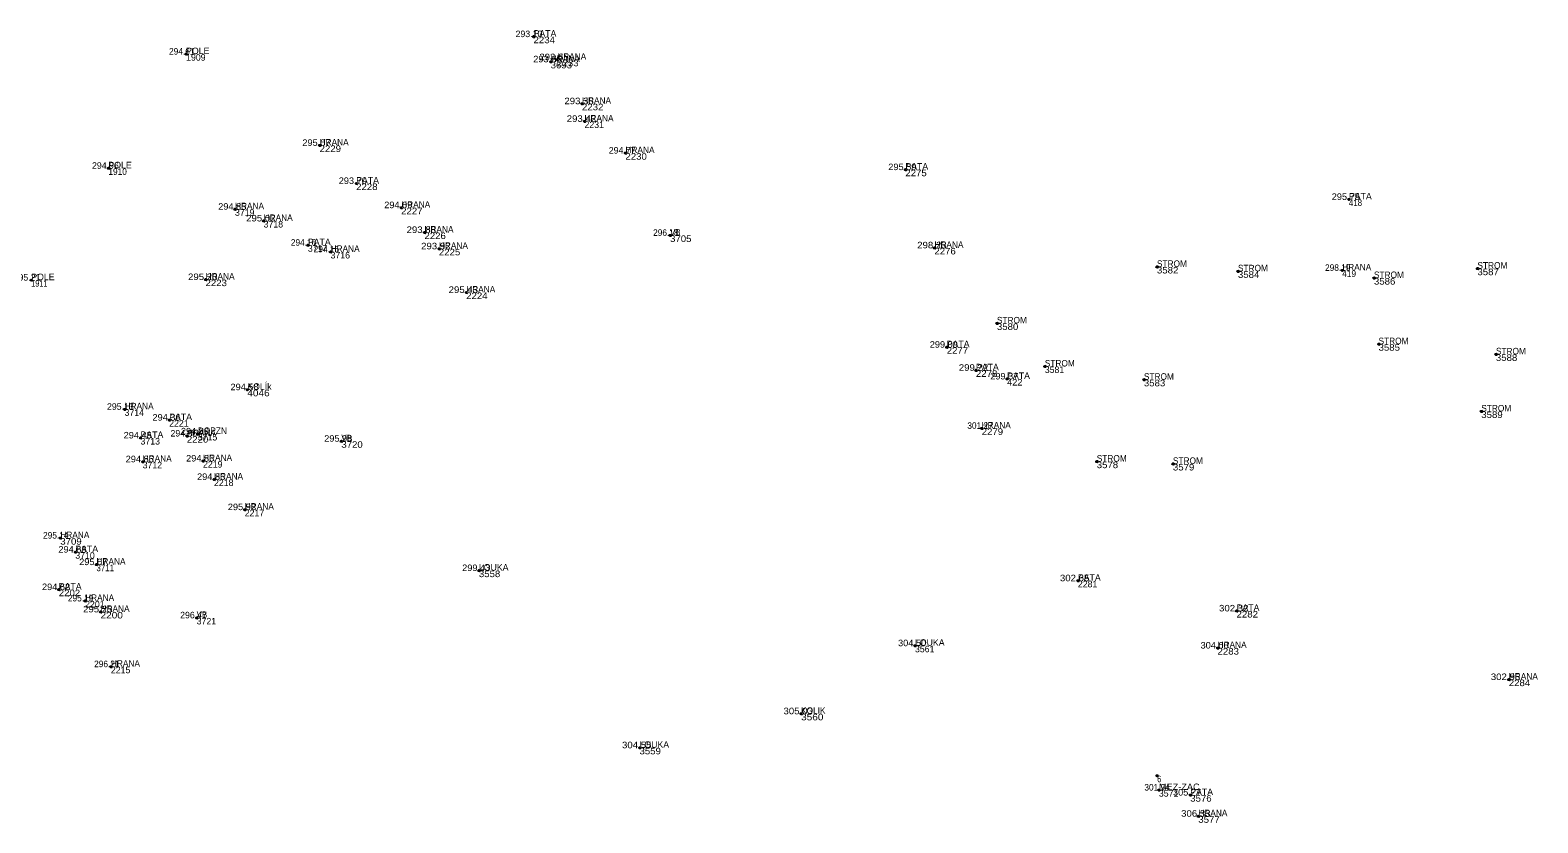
# Model space of a CAD drawing. Extents: x -565336 to -561834, y -1146819 to -1145270.
# Drawn here: x -563916.6 to -563838.2, y -1145848.1 to -1145806.8 of the extents above; entities that cross this region are included whole.
import ezdxf
from ezdxf.enums import TextEntityAlignment as Align

# ---------------------------------------------------------------- set-up
doc = ezdxf.new("R2010")
doc.units = 0
doc.header["$LTSCALE"] = 0.14
doc.header["$PDMODE"] = 32
doc.header["$PDSIZE"] = 0.07
for name, color, linetype in [('40', 7, 'Continuous'), ('43', 7, 'Continuous'), ('44', 7, 'Continuous'), ('45', 7, 'Continuous')]:
    doc.layers.add(name, color=color, linetype=linetype)

msp = doc.modelspace()

# ---------------------------------------------------------------- linework, layer by layer
at = {"layer": '40'}
for p in [(-563890.44, -1145807.15), (-563908.5, -1145808.06), (-563889.55, -1145808.46), (-563889.21, -1145808.35), (-563887.92, -1145810.64), (-563887.79, -1145811.56), (-563901.56, -1145812.81), (-563885.66, -1145813.21), (-563912.54, -1145814), (-563871.11, -1145814.07), (-563899.66, -1145814.79), (-563848.05, -1145815.62), (-563905.96, -1145816.13), (-563897.32, -1145816.05), (-563904.47, -1145816.74), (-563896.11, -1145817.34), (-563902.17, -1145818), (-563895.36, -1145818.19), (-563883.34, -1145817.49), (-563869.6, -1145818.14), (-563900.99, -1145818.35), (-563858.03, -1145819.13), (-563853.82, -1145819.36), (-563848.4, -1145819.31), (-563846.75, -1145819.71), (-563841.37, -1145819.22), (-563916.55, -1145819.82), (-563907.49, -1145819.79), (-563893.94, -1145820.46), (-563866.35, -1145822.07), (-563868.96, -1145823.31), (-563846.51, -1145823.15), (-563840.41, -1145823.68), (-563863.86, -1145824.31), (-563867.44, -1145824.51), (-563865.82, -1145824.96), (-563858.71, -1145825), (-563905.32, -1145825.52), (-563911.7, -1145826.54), (-563841.17, -1145826.65), (-563909.38, -1145827.1), (-563867.14, -1145827.53), (-563910.87, -1145828.03), (-563908.46, -1145827.93), (-563907.89, -1145827.82), (-563900.43, -1145828.2), (-563910.76, -1145829.27), (-563907.62, -1145829.23), (-563861.16, -1145829.26), (-563857.2, -1145829.38), (-563907.05, -1145830.19), (-563905.45, -1145831.76), (-563915.04, -1145833.24), (-563914.26, -1145833.97), (-563913.16, -1145834.62), (-563893.28, -1145834.93), (-563915.12, -1145835.92), (-563862.14, -1145835.46), (-563913.75, -1145836.51), (-563912.95, -1145837.08), (-563907.95, -1145837.39), (-563853.89, -1145837.03), (-563870.61, -1145838.84), (-563854.88, -1145838.96), (-563912.41, -1145839.93), (-563839.74, -1145840.6), (-563876.53, -1145842.38), (-563884.93, -1145844.15), (-563858.02, -1145845.6), (-563857.93, -1145846.35), (-563856.3, -1145846.61), (-563855.88, -1145847.71)]:
    msp.add_point(p, dxfattribs=at)

# ---------------------------------------------------------------- texts
at = {"layer": '43'}
for s, width, p in [('2234', 1.1, (-563890.44, -1145807.49)), ('3693', 1.1, (-563889.55, -1145808.8)), ('2233', 1.1, (-563889.21, -1145808.69)), ('2232', 1.1, (-563887.92, -1145810.98)), ('2229', 1.1, (-563901.56, -1145813.15)), ('2230', 1.1, (-563885.66, -1145813.55)), ('1910', 0.95, (-563912.54, -1145814.34)), ('2275', 1.1, (-563871.11, -1145814.41)), ('2228', 1.1, (-563899.66, -1145815.13)), ('418', 0.9, (-563848.05, -1145815.96)), ('2227', 1.1, (-563897.32, -1145816.39)), ('2226', 1.1, (-563896.11, -1145817.68)), ('3705', 1.1, (-563883.34, -1145817.83)), ('2276', 1.1, (-563869.6, -1145818.48)), ('2225', 1.1, (-563895.36, -1145818.53)), ('3582', 1.1, (-563858.03, -1145819.47)), ('3584', 1.1, (-563853.82, -1145819.7)), ('419', 0.95, (-563848.4, -1145819.65)), ('3586', 1.1, (-563846.75, -1145820.05)), ('3587', 1.1, (-563841.37, -1145819.56)), ('1911', 0.8, (-563916.55, -1145820.16)), ('2223', 1.1, (-563907.49, -1145820.13)), ('2224', 1.1, (-563893.94, -1145820.8)), ('3580', 1.1, (-563866.35, -1145822.41)), ('2277', 1.1, (-563868.96, -1145823.65)), ('3585', 1.1, (-563846.51, -1145823.49)), ('3588', 1.1, (-563840.41, -1145824.02)), ('2278', 1.1, (-563867.44, -1145824.85)), ('422', 1.05, (-563865.82, -1145825.3)), ('3583', 1.1, (-563858.71, -1145825.34)), ('4046', 1.15, (-563905.32, -1145825.86)), ('3589', 1.1, (-563841.17, -1145826.99)), ('2279', 1.1, (-563867.14, -1145827.87)), ('2220', 1.1, (-563908.46, -1145828.27)), ('3720', 1.1, (-563900.43, -1145828.54)), ('3578', 1.1, (-563861.16, -1145829.6)), ('3579', 1.1, (-563857.2, -1145829.72)), ('3709', 1.1, (-563915.04, -1145833.58)), ('3711', 0.9, (-563913.16, -1145834.96)), ('3558', 1.1, (-563893.28, -1145835.27)), ('2202', 1.1, (-563915.12, -1145836.26)), ('2200', 1.15, (-563912.95, -1145837.42)), ('2282', 1.1, (-563853.89, -1145837.37)), ('2283', 1.1, (-563854.88, -1145839.3)), ('2284', 1.1, (-563839.74, -1145840.94)), ('3560', 1.15, (-563876.53, -1145842.72)), ('3559', 1.1, (-563884.93, -1145844.49)), ('6', 0.85, (-563858.02, -1145845.94)), ('3576', 1.1, (-563856.3, -1145846.95)), ('3577', 1.1, (-563855.88, -1145848.05))]:
    msp.add_text(s, height=0.34, dxfattribs=dict(at, width=width)).set_placement(p)
for s, p in [('1909', (-563908.5, -1145808.4)), ('2231', (-563887.79, -1145811.9)), ('3719', (-563905.96, -1145816.47)), ('3718', (-563904.47, -1145817.08)), ('3717', (-563902.17, -1145818.34)), ('3716', (-563900.99, -1145818.69)), ('3581', (-563863.86, -1145824.65)), ('3714', (-563911.7, -1145826.88)), ('2221', (-563909.38, -1145827.44)), ('3713', (-563910.87, -1145828.37)), ('3715', (-563907.89, -1145828.16)), ('3712', (-563910.76, -1145829.61)), ('2219', (-563907.62, -1145829.57)), ('2218', (-563907.05, -1145830.53)), ('2217', (-563905.45, -1145832.1)), ('3710', (-563914.26, -1145834.31)), ('2281', (-563862.14, -1145835.8)), ('2201', (-563913.75, -1145836.85)), ('3721', (-563907.95, -1145837.73)), ('3561', (-563870.61, -1145839.18)), ('2215', (-563912.41, -1145840.27)), ('3571', (-563857.93, -1145846.69))]:
    msp.add_text(s, height=0.34, dxfattribs=at).set_placement(p)
at = {"layer": '44'}
for s, p in [('293.10', (-563890.677, -1145807.174)), ('294.77', (-563885.8315, -1145813.234)), ('294.96', (-563912.695, -1145814.024)), ('295.21', (-563916.7695, -1145819.844)), ('295.13', (-563911.917, -1145826.564)), ('294.96', (-563908.615, -1145827.954)), ('296.47', (-563908.1135, -1145837.414))]:
    msp.add_text(s, height=0.34, dxfattribs=at).set_placement(p, align=Align.CENTER)
for s, width, p in [('294.61', 0.95, (-563908.725, -1145808.084)), ('293.66', 1.05, (-563889.7225, -1145808.484)), ('293.65', 1.1, (-563889.3735, -1145808.374)), ('293.38', 1.1, (-563888.0715, -1145810.664)), ('293.42', 1.1, (-563887.948, -1145811.584)), ('295.07', 1.05, (-563901.7275, -1145812.834)), ('295.59', 1.05, (-563871.2655, -1145814.094)), ('293.70', 1.05, (-563899.8355, -1145814.814)), ('294.85', 1.05, (-563906.1005, -1145816.154)), ('294.09', 1.05, (-563897.47, -1145816.074)), ('295.75', 1.05, (-563848.2135, -1145815.644)), ('295.02', 1.1, (-563904.6145, -1145816.764)), ('293.88', 1.1, (-563896.2735, -1145817.364)), ('296.18', 0.95, (-563883.561, -1145817.514)), ('294.16', 0.95, (-563902.395, -1145818.024)), ('294.15', 0.95, (-563901.2055, -1145818.374)), ('293.92', 1.1, (-563895.518, -1145818.214)), ('298.23', 1.1, (-563869.7285, -1145818.164)), ('295.20', 1.1, (-563907.6345, -1145819.814)), ('298.19', 0.95, (-563848.6305, -1145819.334)), ('295.43', 1.1, (-563894.0875, -1145820.484)), ('299.09', 1.05, (-563869.11, -1145823.334)), ('299.22', 1.1, (-563867.566, -1145824.534)), ('294.58', 1.05, (-563905.462, -1145825.544)), ('299.37', 1.05, (-563865.966, -1145824.984)), ('294.36', 1.05, (-563909.518, -1145827.124)), ('294.89', 1.05, (-563908.04, -1145827.844)), ('301.27', 0.95, (-563867.227, -1145827.554)), ('294.45', 1.05, (-563911.016, -1145828.054)), ('295.98', 1.05, (-563900.5905, -1145828.224)), ('294.86', 1.05, (-563910.91, -1145829.294)), ('294.86', 1.05, (-563907.77, -1145829.254)), ('294.86', 1.05, (-563907.2, -1145830.214)), ('295.92', 1.05, (-563905.6, -1145831.784)), ('295.14', 0.95, (-563915.2745, -1145833.264)), ('294.68', 1.05, (-563914.411, -1145833.994)), ('295.07', 1.05, (-563913.3275, -1145834.644)), ('299.43', 1.05, (-563893.418, -1145834.954)), ('302.65', 1.1, (-563862.309, -1145835.484)), ('294.62', 1.05, (-563915.2605, -1145835.944)), ('295.19', 0.95, (-563913.9845, -1145836.534)), ('295.25', 1.1, (-563913.0905, -1145837.104)), ('302.32', 1.1, (-563854.036, -1145837.054)), ('304.50', 1.05, (-563870.7585, -1145838.864)), ('304.00', 1.05, (-563855.0325, -1145838.984)), ('296.21', 0.95, (-563912.62, -1145839.954)), ('302.95', 1.1, (-563839.909, -1145840.624)), ('305.03', 1.1, (-563876.68, -1145842.404)), ('304.55', 1.1, (-563885.0745, -1145844.174)), ('301.94', 0.95, (-563858.0235, -1145846.374)), ('305.27', 1.05, (-563856.466, -1145846.634)), ('306.33', 1.1, (-563856.0085, -1145847.734))]:
    msp.add_text(s, height=0.34, dxfattribs=dict(at, width=width)).set_placement(p, align=Align.CENTER)
at = {"layer": '45'}
for s, p in [('PATA', (-563890.44, -1145807.15)), ('POLE', (-563908.5, -1145808.06)), ('POLE', (-563912.54, -1145814)), ('PATA', (-563871.11, -1145814.07)), ('PATA', (-563899.66, -1145814.79)), ('PATA', (-563848.05, -1145815.62)), ('PATA', (-563902.17, -1145818)), ('POLE', (-563916.55, -1145819.82)), ('PATA', (-563868.96, -1145823.31)), ('PATA', (-563867.44, -1145824.51)), ('KOLÍk', (-563905.32, -1145825.52)), ('PATA', (-563865.82, -1145824.96)), ('PATA', (-563909.38, -1145827.1)), ('PATA', (-563910.87, -1145828.03)), ('PATA', (-563914.26, -1145833.97)), ('LOUKA', (-563893.28, -1145834.93)), ('PATA', (-563862.14, -1145835.46)), ('PATA', (-563915.12, -1145835.92)), ('PATA', (-563853.89, -1145837.03)), ('LOUKA', (-563870.61, -1145838.84)), ('LOUKA', (-563884.93, -1145844.15)), ('PATA', (-563856.3, -1145846.61))]:
    msp.add_text(s, height=0.34, dxfattribs=at).set_placement(p)
for s, width, p in [('HRANA', 0.95, (-563889.55, -1145808.46)), ('HRANA', 0.95, (-563889.21, -1145808.35)), ('HRANA', 0.95, (-563887.92, -1145810.64)), ('HRANA', 0.95, (-563887.79, -1145811.56)), ('HRANA', 0.95, (-563901.56, -1145812.81)), ('HRANA', 0.95, (-563885.66, -1145813.21)), ('HRANA', 0.95, (-563905.96, -1145816.13)), ('HRANA', 0.95, (-563897.32, -1145816.05)), ('HRANA', 0.95, (-563904.47, -1145816.74)), ('HRANA', 0.95, (-563896.11, -1145817.34)), ('VB', 0.9, (-563883.34, -1145817.49)), ('HRANA', 0.95, (-563900.99, -1145818.35)), ('HRANA', 0.95, (-563895.36, -1145818.19)), ('HRANA', 0.95, (-563869.6, -1145818.14)), ('STROM', 0.95, (-563858.03, -1145819.13)), ('STROM', 0.95, (-563841.37, -1145819.22)), ('HRANA', 0.95, (-563907.49, -1145819.79)), ('STROM', 0.95, (-563853.82, -1145819.36)), ('HRANA', 0.95, (-563848.4, -1145819.31)), ('STROM', 0.95, (-563846.75, -1145819.71)), ('HRANA', 0.95, (-563893.94, -1145820.46)), ('STROM', 0.95, (-563866.35, -1145822.07)), ('STROM', 0.95, (-563846.51, -1145823.15)), ('STROM', 0.95, (-563840.41, -1145823.68)), ('STROM', 0.95, (-563863.86, -1145824.31)), ('STROM', 0.95, (-563858.71, -1145825)), ('HRANA', 0.95, (-563911.7, -1145826.54)), ('STROM', 0.95, (-563841.17, -1145826.65)), ('DOPZN', 0.95, (-563907.89, -1145827.82)), ('HRANA', 0.95, (-563867.14, -1145827.53)), ('HRANA', 0.95, (-563908.46, -1145827.93)), ('VB', 0.9, (-563900.43, -1145828.2)), ('HRANA', 0.95, (-563910.76, -1145829.27)), ('HRANA', 0.95, (-563907.62, -1145829.23)), ('STROM', 0.95, (-563861.16, -1145829.26)), ('STROM', 0.95, (-563857.2, -1145829.38)), ('HRANA', 0.95, (-563907.05, -1145830.19)), ('HRANA', 0.95, (-563905.45, -1145831.76)), ('HRANA', 0.95, (-563915.04, -1145833.24)), ('HRANA', 0.95, (-563913.16, -1145834.62)), ('HRANA', 0.95, (-563913.75, -1145836.51)), ('HRANA', 0.95, (-563912.95, -1145837.08)), ('VB', 0.9, (-563907.95, -1145837.39)), ('HRANA', 0.95, (-563854.88, -1145838.96)), ('HRANA', 0.95, (-563912.41, -1145839.93)), ('HRANA', 0.95, (-563839.74, -1145840.6)), ('KOLIK', 0.95, (-563876.53, -1145842.38)), ('MEZ-ZAC', 1.05, (-563857.93, -1145846.35)), ('HRANA', 0.95, (-563855.88, -1145847.71))]:
    msp.add_text(s, height=0.34, dxfattribs=dict(at, width=width)).set_placement(p)

doc.saveas('drawing.dxf')
